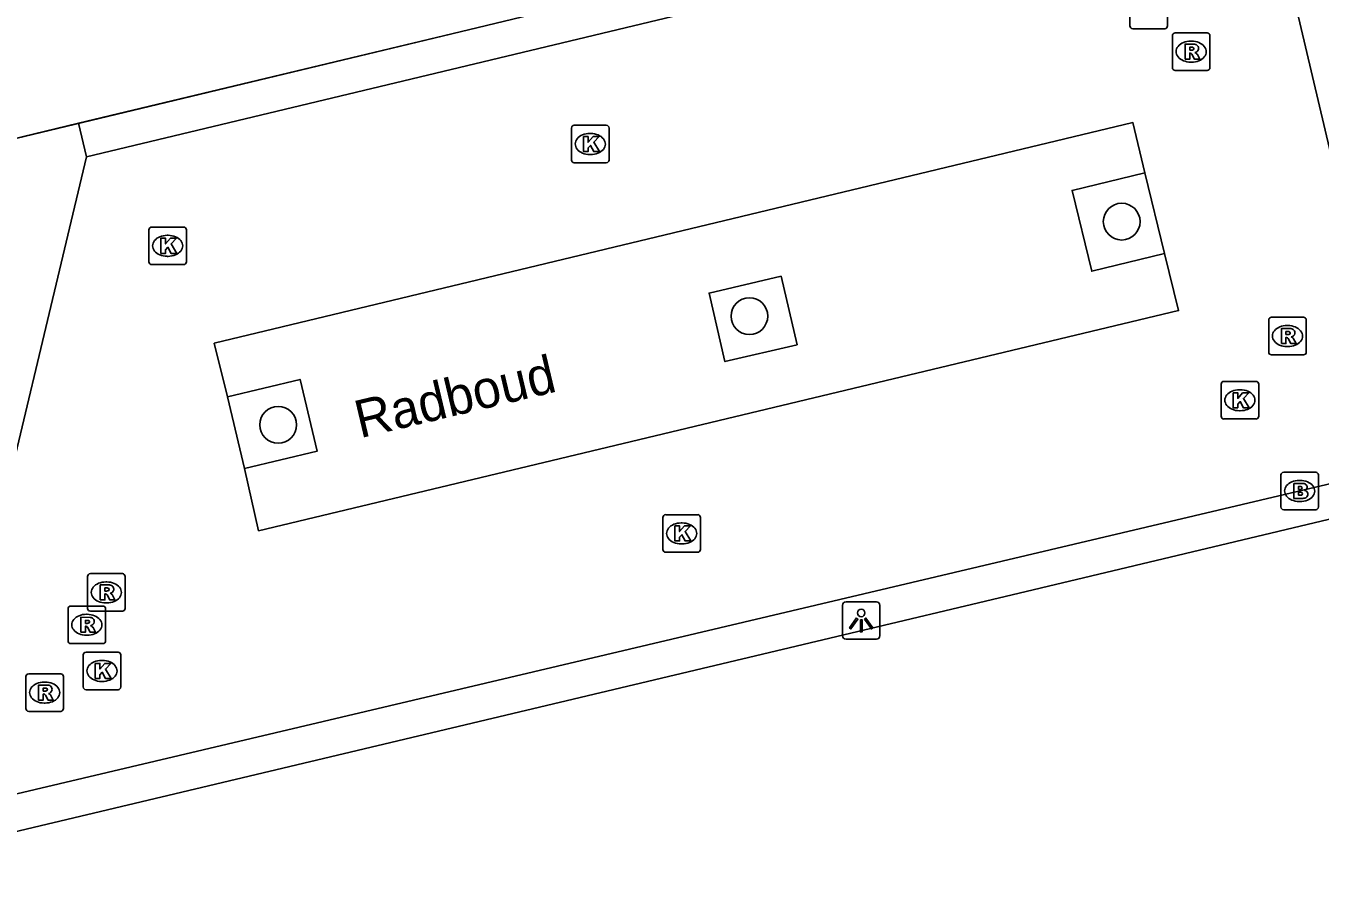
# Model space of a CAD drawing. Extents: x 157663 to 158496, y 379212 to 380934.
# Drawn here: x 158285.62 to 158320.09, y 380832.57 to 380855.17 of the extents above; entities that cross this region are included whole.
import ezdxf

# ---------------------------------------------------------------- set-up
doc = ezdxf.new("R2010")
doc.units = 0
for name, color, linetype in [('IMGEO_Boom', 7, 'Continuous'), ('IMGEO_Brandkraan', 7, 'Continuous'), ('IMGEO_Hek', 7, 'Continuous'), ('IMGEO_Kolk', 7, 'Continuous'), ('IMGEO_Lichtpunt', 7, 'Continuous'), ('IMGEO_Openbare_ruimte_label', 7, 'Continuous'), ('IMGEO_Parkeervlak_open', 7, 'Continuous'), ('IMGEO_Rijbaan_lokaal_open', 7, 'Continuous'), ('IMGEO_Rioolput', 7, 'Continuous'), ('IMGEO_Voetpad_open', 7, 'Continuous')]:
    doc.layers.add(name, color=color, linetype=linetype)

msp = doc.modelspace()

# ---------------------------------------------------------------- linework, layer by layer
at = {"layer": 'IMGEO_Boom'}
for centre in [(158314.804, 380849.964), (158304.889, 380847.448), (158292.339, 380844.556)]:
    msp.add_circle(centre, 0.489, dxfattribs=at)
at = {"layer": 'IMGEO_Brandkraan'}
for p, q in [((158319.044, 380842.368), (158319.044, 380843.22)), ((158319.119, 380843.294), (158319.971, 380843.294)), ((158320.045, 380843.22), (158320.045, 380842.368)), ((158319.532, 380843.074), (158319.557, 380843.074)), ((158319.555, 380842.514), (158319.53, 380842.514)), ((158319.971, 380842.294), (158319.119, 380842.294))]:
    msp.add_line(p, q, dxfattribs=at)
for points in [[(158319.044, 380842.368), (158319.044, 380843.22)], [(158319.119, 380843.294), (158319.971, 380843.294)], [(158320.045, 380843.22), (158320.045, 380842.368)], [(158319.392, 380842.994), (158319.392, 380842.594), (158319.605, 380842.594)], [(158319.623, 380842.994), (158319.392, 380842.994)], [(158319.571, 380842.913), (158319.517, 380842.913), (158319.517, 380842.837)], [(158319.517, 380842.837), (158319.57, 380842.837)], [(158319.579, 380842.761), (158319.517, 380842.761), (158319.517, 380842.68)], [(158319.517, 380842.68), (158319.579, 380842.68)], [(158319.971, 380842.294), (158319.119, 380842.294)]]:
    msp.add_lwpolyline(points, dxfattribs=at)
for centre, radius, start, end in [((158319.121, 380843.218), 0.0765, 91.552, 178.448), ((158319.121, 380843.218), 0.0765, 91.552, 178.448), ((158319.969, 380843.218), 0.0765, 1.552, 88.448), ((158319.969, 380843.218), 0.0765, 1.552, 88.448), ((158319.572, 380842.875), 0.0379, 267.8285, 90.9355), ((158319.58, 380842.72), 0.0404, 269.8759, 90.5077), ((158319.627, 380842.849), 0.145, 59.4692, 91.5367), ((158319.652, 380842.896), 0.0922, 285.5137, 58.1501), ((158319.657, 380842.704), 0.105, 301.3115, 78.989), ((158319.611, 380842.845), 0.251, 268.6676, 293.5347), ((158319.121, 380842.37), 0.0765, 181.552, 268.448), ((158319.121, 380842.37), 0.0765, 181.552, 268.448), ((158319.969, 380842.37), 0.0765, 271.552, 358.448), ((158319.969, 380842.37), 0.0765, 271.552, 358.448)]:
    msp.add_arc(centre, radius, start, end, dxfattribs=at)
for centre, major_axis, ratio, start_param, end_param in [((158319.531, 380842.794), (-0.387, 0.002), 0.722429, 4.712389, 7.853982), ((158319.556, 380842.794), (-0.39, 0.002), 0.717154, 1.570796, 4.712389)]:
    msp.add_ellipse(centre, major_axis=major_axis, ratio=ratio, start_param=start_param, end_param=end_param, dxfattribs=at)
at = {"layer": 'IMGEO_Hek'}
msp.add_lwpolyline([(158296.964, 380854.965), (158284.011, 380851.861)], dxfattribs=at)
at = {"layer": 'IMGEO_Kolk'}
for p, q in [((158315.023, 380855.175), (158315.023, 380856.027)), ((158316.024, 380856.027), (158316.024, 380855.175)), ((158315.95, 380855.101), (158315.098, 380855.101)), ((158300.15, 380851.604), (158300.15, 380852.456)), ((158300.225, 380852.53), (158301.077, 380852.53)), ((158301.151, 380852.456), (158301.151, 380851.604)), ((158300.638, 380852.31), (158300.663, 380852.31)), ((158300.661, 380851.75), (158300.636, 380851.75)), ((158301.077, 380851.53), (158300.225, 380851.53)), ((158288.895, 380848.894), (158288.895, 380849.746)), ((158288.97, 380849.82), (158289.822, 380849.82)), ((158289.896, 380849.746), (158289.896, 380848.894)), ((158289.383, 380849.6), (158289.408, 380849.6)), ((158289.406, 380849.04), (158289.381, 380849.04)), ((158289.822, 380848.82), (158288.97, 380848.82)), ((158317.452, 380844.784), (158317.452, 380845.636)), ((158317.527, 380845.71), (158318.379, 380845.71)), ((158318.453, 380845.636), (158318.453, 380844.784)), ((158317.94, 380845.49), (158317.965, 380845.49)), ((158317.963, 380844.93), (158317.938, 380844.93)), ((158318.379, 380844.71), (158317.527, 380844.71)), ((158302.585, 380841.237), (158302.585, 380842.089)), ((158302.66, 380842.163), (158303.512, 380842.163)), ((158303.586, 380842.089), (158303.586, 380841.237)), ((158303.073, 380841.943), (158303.098, 380841.943)), ((158303.096, 380841.383), (158303.071, 380841.383)), ((158303.512, 380841.163), (158302.66, 380841.163)), ((158287.146, 380837.577), (158287.146, 380838.429)), ((158287.221, 380838.503), (158288.073, 380838.503)), ((158287.634, 380838.283), (158287.659, 380838.283)), ((158288.147, 380838.429), (158288.147, 380837.577)), ((158287.657, 380837.723), (158287.632, 380837.723)), ((158288.073, 380837.503), (158287.221, 380837.503))]:
    msp.add_line(p, q, dxfattribs=at)
for points in [[(158315.023, 380855.175), (158315.023, 380856.027)], [(158316.024, 380856.027), (158316.024, 380855.175)], [(158315.95, 380855.101), (158315.098, 380855.101)], [(158300.15, 380851.604), (158300.15, 380852.456)], [(158300.225, 380852.53), (158301.077, 380852.53)], [(158301.151, 380852.456), (158301.151, 380851.604)], [(158300.471, 380852.23), (158300.594, 380852.23), (158300.594, 380852.079), (158300.724, 380852.23), (158300.888, 380852.23), (158300.742, 380852.079), (158300.895, 380851.83), (158300.743, 380851.83), (158300.658, 380851.994), (158300.594, 380851.927), (158300.594, 380851.83), (158300.471, 380851.83), (158300.471, 380852.23)], [(158301.077, 380851.53), (158300.225, 380851.53)], [(158288.895, 380848.894), (158288.895, 380849.746)], [(158288.97, 380849.82), (158289.822, 380849.82)], [(158289.896, 380849.746), (158289.896, 380848.894)], [(158289.216, 380849.52), (158289.339, 380849.52), (158289.339, 380849.369), (158289.469, 380849.52), (158289.633, 380849.52), (158289.487, 380849.369), (158289.64, 380849.12), (158289.488, 380849.12), (158289.403, 380849.284), (158289.339, 380849.217), (158289.339, 380849.12), (158289.216, 380849.12), (158289.216, 380849.52)], [(158289.822, 380848.82), (158288.97, 380848.82)], [(158317.452, 380844.784), (158317.452, 380845.636)], [(158317.527, 380845.71), (158318.379, 380845.71)], [(158318.453, 380845.636), (158318.453, 380844.784)], [(158317.773, 380845.41), (158317.896, 380845.41), (158317.896, 380845.259), (158318.026, 380845.41), (158318.19, 380845.41), (158318.044, 380845.259), (158318.197, 380845.01), (158318.045, 380845.01), (158317.96, 380845.174), (158317.896, 380845.107), (158317.896, 380845.01), (158317.773, 380845.01), (158317.773, 380845.41)], [(158318.379, 380844.71), (158317.527, 380844.71)], [(158302.585, 380841.237), (158302.585, 380842.089)], [(158302.66, 380842.163), (158303.512, 380842.163)], [(158303.586, 380842.089), (158303.586, 380841.237)], [(158302.906, 380841.863), (158303.029, 380841.863), (158303.029, 380841.712), (158303.159, 380841.863), (158303.323, 380841.863), (158303.177, 380841.712), (158303.33, 380841.463), (158303.178, 380841.463), (158303.093, 380841.627), (158303.029, 380841.56), (158303.029, 380841.463), (158302.906, 380841.463), (158302.906, 380841.863)], [(158303.512, 380841.163), (158302.66, 380841.163)], [(158287.146, 380837.577), (158287.146, 380838.429)], [(158287.221, 380838.503), (158288.073, 380838.503)], [(158288.147, 380838.429), (158288.147, 380837.577)], [(158287.467, 380838.203), (158287.59, 380838.203), (158287.59, 380838.052), (158287.72, 380838.203), (158287.884, 380838.203), (158287.738, 380838.052), (158287.891, 380837.803), (158287.739, 380837.803), (158287.654, 380837.967), (158287.59, 380837.9), (158287.59, 380837.803), (158287.467, 380837.803), (158287.467, 380838.203)], [(158288.073, 380837.503), (158287.221, 380837.503)]]:
    msp.add_lwpolyline(points, dxfattribs=at)
for centre, start, end in [((158315.1, 380855.177), 181.552, 268.448), ((158315.1, 380855.177), 181.552, 268.448), ((158315.948, 380855.177), 271.552, 358.448), ((158315.948, 380855.177), 271.552, 358.448), ((158300.227, 380852.454), 91.552, 178.448), ((158300.227, 380852.454), 91.552, 178.448), ((158301.075, 380852.454), 1.552, 88.448), ((158301.075, 380852.454), 1.552, 88.448), ((158300.227, 380851.606), 181.552, 268.448), ((158300.227, 380851.606), 181.552, 268.448), ((158301.075, 380851.606), 271.552, 358.448), ((158301.075, 380851.606), 271.552, 358.448), ((158288.972, 380849.744), 91.552, 178.448), ((158288.972, 380849.744), 91.552, 178.448), ((158289.82, 380849.744), 1.552, 88.448), ((158289.82, 380849.744), 1.552, 88.448), ((158288.972, 380848.896), 181.552, 268.448), ((158288.972, 380848.896), 181.552, 268.448), ((158289.82, 380848.896), 271.552, 358.448), ((158289.82, 380848.896), 271.552, 358.448), ((158317.529, 380845.634), 91.552, 178.448), ((158317.529, 380845.634), 91.552, 178.448), ((158318.377, 380845.634), 1.552, 88.448), ((158318.377, 380845.634), 1.552, 88.448), ((158317.529, 380844.786), 181.552, 268.448), ((158317.529, 380844.786), 181.552, 268.448), ((158318.377, 380844.786), 271.552, 358.448), ((158318.377, 380844.786), 271.552, 358.448), ((158302.662, 380842.087), 91.552, 178.448), ((158302.662, 380842.087), 91.552, 178.448), ((158303.51, 380842.087), 1.552, 88.448), ((158303.51, 380842.087), 1.552, 88.448), ((158302.662, 380841.239), 181.552, 268.448), ((158302.662, 380841.239), 181.552, 268.448), ((158303.51, 380841.239), 271.552, 358.448), ((158303.51, 380841.239), 271.552, 358.448), ((158287.223, 380838.427), 91.552, 178.448), ((158287.223, 380838.427), 91.552, 178.448), ((158288.071, 380838.427), 1.552, 88.448), ((158288.071, 380838.427), 1.552, 88.448), ((158287.223, 380837.579), 181.552, 268.448), ((158287.223, 380837.579), 181.552, 268.448), ((158288.071, 380837.579), 271.552, 358.448), ((158288.071, 380837.579), 271.552, 358.448)]:
    msp.add_arc(centre, 0.0765, start, end, dxfattribs=at)
for centre, major_axis, ratio, start_param, end_param in [((158300.637, 380852.03), (-0.387, 0.002), 0.722429, 4.712389, 7.853982), ((158300.662, 380852.03), (-0.39, 0.002), 0.717154, 1.570796, 4.712389), ((158289.382, 380849.32), (-0.387, 0.002), 0.722429, 4.712389, 7.853982), ((158289.407, 380849.32), (-0.39, 0.002), 0.717154, 1.570796, 4.712389), ((158317.939, 380845.21), (-0.387, 0.002), 0.722429, 4.712389, 7.853982), ((158317.964, 380845.21), (-0.39, 0.002), 0.717154, 1.570796, 4.712389), ((158303.072, 380841.663), (-0.387, 0.002), 0.722429, 4.712389, 7.853982), ((158303.097, 380841.663), (-0.39, 0.002), 0.717154, 1.570796, 4.712389), ((158287.633, 380838.003), (-0.387, 0.002), 0.722429, 4.712389, 7.853982), ((158287.658, 380838.003), (-0.39, 0.002), 0.717154, 1.570796, 4.712389)]:
    msp.add_ellipse(centre, major_axis=major_axis, ratio=ratio, start_param=start_param, end_param=end_param, dxfattribs=at)
at = {"layer": 'IMGEO_Lichtpunt'}
for p, q in [((158307.368, 380839.749), (158307.368, 380838.942)), ((158307.368, 380839.749), (158307.368, 380838.942)), ((158308.27, 380839.844), (158307.462, 380839.844)), ((158308.27, 380839.844), (158307.462, 380839.844)), ((158308.364, 380838.942), (158308.364, 380839.749)), ((158308.364, 380838.942), (158308.364, 380839.749)), ((158307.462, 380838.848), (158308.27, 380838.848)), ((158307.462, 380838.848), (158308.27, 380838.848))]:
    msp.add_line(p, q, dxfattribs=at)
for points in [[(158307.742, 380839.413), (158307.781, 380839.385), (158307.593, 380839.123), (158307.555, 380839.15), (158307.742, 380839.413)], [(158307.844, 380839.365), (158307.891, 380839.365), (158307.891, 380839.043), (158307.844, 380839.043), (158307.844, 380839.365)], [(158307.954, 380839.385), (158307.992, 380839.412), (158308.179, 380839.15), (158308.14, 380839.122), (158307.954, 380839.385)]]:
    msp.add_lwpolyline(points, dxfattribs=at)
msp.add_circle((158307.867, 380839.547), 0.0994, dxfattribs=at)
for centre, start, end in [((158307.462, 380839.749), 90, 180), ((158307.462, 380839.749), 90, 180), ((158308.27, 380839.749), 0, 90), ((158308.27, 380839.749), 0, 90), ((158307.462, 380838.942), 180, 270), ((158307.462, 380838.942), 180, 270), ((158308.27, 380838.942), 270, 0), ((158308.27, 380838.942), 270, 360)]:
    msp.add_arc(centre, 0.0946, start, end, dxfattribs=at)
at = {"layer": 'IMGEO_Parkeervlak_open'}
for points in [[(158315.418, 380851.267), (158313.483, 380850.797), (158314.005, 380848.644), (158315.94, 380849.113)], [(158306.16, 380846.686), (158304.239, 380846.237), (158303.813, 380848.06), (158305.733, 380848.51), (158306.16, 380846.686)], [(158290.989, 380845.302), (158292.923, 380845.765), (158293.38, 380843.855), (158291.446, 380843.392)]]:
    msp.add_lwpolyline(points, dxfattribs=at)
at = {"layer": 'IMGEO_Rijbaan_lokaal_open'}
for points in [[(158287.237, 380851.686), (158311.51, 380857.513), (158313.386, 380859.917), (158311.628, 380867.312), (158323.395, 380870.062), (158323.37, 380870.177), (158324.642, 380870.454), (158326.838, 380874.024), (158334.173, 380875.639)], [(158335.841, 380868.585), (158317.438, 380864.207), (158322.34, 380843.453), (158256.423, 380827.895), (158256.672, 380826.915)], [(158315.418, 380851.267), (158315.104, 380852.601), (158290.638, 380846.728), (158290.989, 380845.302)], [(158282.13, 380839.078), (158284.341, 380839.582), (158287.237, 380851.686)], [(158315.94, 380849.113), (158315.418, 380851.267)], [(158291.446, 380843.392), (158291.818, 380841.736), (158316.319, 380847.596), (158315.94, 380849.113)], [(158290.989, 380845.302), (158291.446, 380843.392)]]:
    msp.add_lwpolyline(points, dxfattribs=at)
at = {"layer": 'IMGEO_Rioolput'}
for p, q in [((158316.154, 380854.063), (158316.154, 380854.915)), ((158316.229, 380854.989), (158317.081, 380854.989)), ((158317.155, 380854.915), (158317.155, 380854.063)), ((158316.642, 380854.769), (158316.667, 380854.769)), ((158316.665, 380854.209), (158316.64, 380854.209)), ((158317.081, 380853.989), (158316.229, 380853.989)), ((158318.719, 380846.492), (158318.719, 380847.344)), ((158318.794, 380847.418), (158319.646, 380847.418)), ((158319.72, 380847.344), (158319.72, 380846.492)), ((158319.207, 380847.198), (158319.232, 380847.198)), ((158319.23, 380846.638), (158319.205, 380846.638)), ((158319.646, 380846.418), (158318.794, 380846.418)), ((158287.262, 380839.667), (158287.262, 380840.519)), ((158287.337, 380840.593), (158288.189, 380840.593)), ((158287.75, 380840.373), (158287.775, 380840.373)), ((158288.263, 380840.519), (158288.263, 380839.667)), ((158286.742, 380838.805), (158286.742, 380839.657)), ((158286.817, 380839.731), (158287.669, 380839.731)), ((158287.743, 380839.657), (158287.743, 380838.805)), ((158287.773, 380839.813), (158287.748, 380839.813)), ((158287.23, 380839.511), (158287.255, 380839.511)), ((158288.189, 380839.593), (158287.337, 380839.593)), ((158287.253, 380838.951), (158287.228, 380838.951)), ((158287.669, 380838.731), (158286.817, 380838.731)), ((158285.694, 380837.927), (158286.546, 380837.927)), ((158285.619, 380837.001), (158285.619, 380837.853)), ((158286.107, 380837.707), (158286.132, 380837.707)), ((158286.62, 380837.853), (158286.62, 380837.001)), ((158286.546, 380836.927), (158285.694, 380836.927)), ((158286.13, 380837.147), (158286.105, 380837.147))]:
    msp.add_line(p, q, dxfattribs=at)
for points in [[(158316.154, 380854.063), (158316.154, 380854.915)], [(158316.229, 380854.989), (158317.081, 380854.989)], [(158317.155, 380854.915), (158317.155, 380854.063)], [(158316.743, 380854.687), (158316.491, 380854.689), (158316.491, 380854.289)], [(158316.669, 380854.608), (158316.615, 380854.608), (158316.615, 380854.527)], [(158316.615, 380854.527), (158316.667, 380854.527)], [(158316.491, 380854.289), (158316.615, 380854.289), (158316.615, 380854.451), (158316.626, 380854.451)], [(158316.673, 380854.422), (158316.744, 380854.289), (158316.884, 380854.289), (158316.819, 380854.415)], [(158317.081, 380853.989), (158316.229, 380853.989)], [(158318.719, 380846.492), (158318.719, 380847.344)], [(158318.794, 380847.418), (158319.646, 380847.418)], [(158319.72, 380847.344), (158319.72, 380846.492)], [(158319.308, 380847.116), (158319.056, 380847.118), (158319.056, 380846.718)], [(158319.056, 380846.718), (158319.18, 380846.718), (158319.18, 380846.88), (158319.191, 380846.88)], [(158319.234, 380847.037), (158319.18, 380847.037), (158319.18, 380846.956)], [(158319.18, 380846.956), (158319.232, 380846.956)], [(158319.238, 380846.851), (158319.309, 380846.718), (158319.449, 380846.718), (158319.384, 380846.844)], [(158319.646, 380846.418), (158318.794, 380846.418)], [(158287.262, 380839.667), (158287.262, 380840.519)], [(158287.337, 380840.593), (158288.189, 380840.593)], [(158288.263, 380840.519), (158288.263, 380839.667)], [(158287.851, 380840.291), (158287.599, 380840.293), (158287.599, 380839.893)], [(158287.599, 380839.893), (158287.723, 380839.893), (158287.723, 380840.055), (158287.734, 380840.055)], [(158287.777, 380840.212), (158287.723, 380840.212), (158287.723, 380840.131)], [(158287.723, 380840.131), (158287.775, 380840.131)], [(158287.781, 380840.026), (158287.852, 380839.893), (158287.992, 380839.893), (158287.927, 380840.019)], [(158286.742, 380838.805), (158286.742, 380839.657)], [(158286.817, 380839.731), (158287.669, 380839.731)], [(158287.743, 380839.657), (158287.743, 380838.805)], [(158287.331, 380839.429), (158287.079, 380839.431), (158287.079, 380839.031)], [(158287.257, 380839.35), (158287.203, 380839.35), (158287.203, 380839.269)], [(158288.189, 380839.593), (158287.337, 380839.593)], [(158287.079, 380839.031), (158287.203, 380839.031), (158287.203, 380839.193), (158287.214, 380839.193)], [(158287.203, 380839.269), (158287.255, 380839.269)], [(158287.261, 380839.164), (158287.332, 380839.031), (158287.472, 380839.031), (158287.407, 380839.157)], [(158287.669, 380838.731), (158286.817, 380838.731)], [(158285.694, 380837.927), (158286.546, 380837.927)], [(158285.619, 380837.001), (158285.619, 380837.853)], [(158286.208, 380837.625), (158285.956, 380837.627), (158285.956, 380837.227)], [(158286.62, 380837.853), (158286.62, 380837.001)], [(158285.956, 380837.227), (158286.08, 380837.227), (158286.08, 380837.389), (158286.091, 380837.389)], [(158286.134, 380837.546), (158286.08, 380837.546), (158286.08, 380837.465)], [(158286.08, 380837.465), (158286.132, 380837.465)], [(158286.138, 380837.36), (158286.209, 380837.227), (158286.349, 380837.227), (158286.284, 380837.353)], [(158286.546, 380836.927), (158285.694, 380836.927)]]:
    msp.add_lwpolyline(points, dxfattribs=at)
for centre, radius, start, end in [((158316.231, 380854.913), 0.0765, 91.552, 178.448), ((158316.231, 380854.913), 0.0765, 91.552, 178.448), ((158317.079, 380854.913), 0.0765, 1.552, 88.448), ((158317.079, 380854.913), 0.0765, 1.552, 88.448), ((158316.651, 380854.716), 0.19, 274.7715, 282.9687), ((158316.675, 380854.512), 0.0964, 77.0061, 93.1865), ((158316.689, 380854.569), 0.0378, 276.6634, 79.6772), ((158316.742, 380854.577), 0.109, 350.3612, 89.416), ((158316.74, 380854.577), 0.112, 277.5842, 350.9817), ((158316.724, 380854.362), 0.108, 29.5134, 73.7905), ((158316.625, 380854.398), 0.0533, 26.0293, 88.6989), ((158316.231, 380854.065), 0.0765, 181.552, 268.448), ((158316.231, 380854.065), 0.0765, 181.552, 268.448), ((158317.079, 380854.065), 0.0765, 271.552, 358.448), ((158317.079, 380854.065), 0.0765, 271.552, 358.448), ((158318.796, 380847.342), 0.0765, 91.552, 178.448), ((158318.796, 380847.342), 0.0765, 91.552, 178.448), ((158319.644, 380847.342), 0.0765, 1.552, 88.448), ((158319.644, 380847.342), 0.0765, 1.552, 88.448), ((158319.19, 380846.827), 0.0533, 26.0293, 88.6989), ((158319.216, 380847.145), 0.19, 274.7715, 282.9687), ((158319.24, 380846.941), 0.0964, 77.0061, 93.1865), ((158319.254, 380846.998), 0.0378, 276.6634, 79.6772), ((158319.307, 380847.006), 0.109, 350.3612, 89.416), ((158319.305, 380847.006), 0.112, 277.5842, 350.9817), ((158319.289, 380846.791), 0.108, 29.5134, 73.7905), ((158318.796, 380846.494), 0.0765, 181.552, 268.448), ((158318.796, 380846.494), 0.0765, 181.552, 268.448), ((158319.644, 380846.494), 0.0765, 271.552, 358.448), ((158319.644, 380846.494), 0.0765, 271.552, 358.448), ((158287.339, 380840.517), 0.0765, 91.552, 178.448), ((158287.339, 380840.517), 0.0765, 91.552, 178.448), ((158288.187, 380840.517), 0.0765, 1.552, 88.448), ((158288.187, 380840.517), 0.0765, 1.552, 88.448), ((158287.733, 380840.002), 0.0533, 26.0293, 88.6989), ((158287.759, 380840.32), 0.19, 274.7715, 282.9687), ((158287.783, 380840.116), 0.0964, 77.0061, 93.1865), ((158287.797, 380840.173), 0.0378, 276.6634, 79.6772), ((158287.85, 380840.181), 0.109, 350.3612, 89.416), ((158287.848, 380840.181), 0.112, 277.5842, 350.9817), ((158287.832, 380839.966), 0.108, 29.5134, 73.7905), ((158286.819, 380839.655), 0.0765, 91.552, 178.448), ((158286.819, 380839.655), 0.0765, 91.552, 178.448), ((158287.339, 380839.669), 0.0765, 181.552, 268.448), ((158287.339, 380839.669), 0.0765, 181.552, 268.448), ((158287.667, 380839.655), 0.0765, 1.552, 88.448), ((158287.667, 380839.655), 0.0765, 1.552, 88.448), ((158288.187, 380839.669), 0.0765, 271.552, 358.448), ((158288.187, 380839.669), 0.0765, 271.552, 358.448), ((158287.263, 380839.254), 0.0964, 77.0061, 93.1865), ((158287.277, 380839.311), 0.0378, 276.6634, 79.6772), ((158287.33, 380839.319), 0.109, 350.3612, 89.416), ((158287.328, 380839.319), 0.112, 277.5842, 350.9817), ((158287.213, 380839.14), 0.0533, 26.0293, 88.6989), ((158287.239, 380839.458), 0.19, 274.7715, 282.9687), ((158287.312, 380839.104), 0.108, 29.5134, 73.7905), ((158286.819, 380838.807), 0.0765, 181.552, 268.448), ((158286.819, 380838.807), 0.0765, 181.552, 268.448), ((158287.667, 380838.807), 0.0765, 271.552, 358.448), ((158287.667, 380838.807), 0.0765, 271.552, 358.448), ((158285.696, 380837.851), 0.0765, 91.552, 178.448), ((158285.696, 380837.851), 0.0765, 91.552, 178.448), ((158286.544, 380837.851), 0.0765, 1.552, 88.448), ((158286.544, 380837.851), 0.0765, 1.552, 88.448), ((158286.207, 380837.515), 0.109, 350.3612, 89.416), ((158286.09, 380837.336), 0.0533, 26.0293, 88.6989), ((158286.116, 380837.654), 0.19, 274.7715, 282.9687), ((158286.14, 380837.45), 0.0964, 77.0061, 93.1865), ((158286.154, 380837.507), 0.0378, 276.6634, 79.6772), ((158286.205, 380837.515), 0.112, 277.5842, 350.9817), ((158286.189, 380837.3), 0.108, 29.5134, 73.7905), ((158285.696, 380837.003), 0.0765, 181.552, 268.448), ((158285.696, 380837.003), 0.0765, 181.552, 268.448), ((158286.544, 380837.003), 0.0765, 271.552, 358.448), ((158286.544, 380837.003), 0.0765, 271.552, 358.448)]:
    msp.add_arc(centre, radius, start, end, dxfattribs=at)
for centre, major_axis, ratio, start_param, end_param in [((158316.641, 380854.489), (-0.387, 0.002), 0.722429, 4.712389, 7.853982), ((158316.666, 380854.489), (-0.39, 0.002), 0.717154, 1.570796, 4.712389), ((158319.206, 380846.918), (-0.387, 0.002), 0.722429, 4.712389, 7.853982), ((158319.231, 380846.918), (-0.39, 0.002), 0.717154, 1.570796, 4.712389), ((158287.749, 380840.093), (-0.387, 0.002), 0.722429, 4.712389, 7.853982), ((158287.774, 380840.093), (-0.39, 0.002), 0.717154, 1.570796, 4.712389), ((158287.229, 380839.231), (-0.387, 0.002), 0.722429, 4.712389, 7.853982), ((158287.254, 380839.231), (-0.39, 0.002), 0.717154, 1.570796, 4.712389), ((158286.106, 380837.427), (-0.387, 0.002), 0.722429, 4.712389, 7.853982), ((158286.131, 380837.427), (-0.39, 0.002), 0.717154, 1.570796, 4.712389)]:
    msp.add_ellipse(centre, major_axis=major_axis, ratio=ratio, start_param=start_param, end_param=end_param, dxfattribs=at)
at = {"layer": 'IMGEO_Voetpad_open'}
for points in [[(158271.67, 380888.542), (158276.061, 380869.995), (158278.992, 380870.719), (158280.865, 380862.903), (158283.487, 380851.735), (158284.011, 380851.861), (158287.022, 380852.583)], [(158287.022, 380852.583), (158296.964, 380854.965), (158302.979, 380856.415), (158306.319, 380857.198)], [(158287.237, 380851.686), (158287.022, 380852.583)], [(158321.058, 380841.488), (158320.897, 380842.175), (158312.07, 380840.074), (158256.672, 380826.915)]]:
    msp.add_lwpolyline(points, dxfattribs=at)

# ---------------------------------------------------------------- texts
at = {"layer": 'IMGEO_Openbare_ruimte_label'}
msp.add_text('Radboud', height=1, rotation=13.3553, dxfattribs=at).set_placement((158294.518, 380844.195))

doc.saveas('drawing.dxf')
